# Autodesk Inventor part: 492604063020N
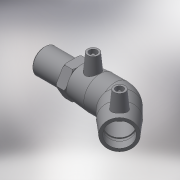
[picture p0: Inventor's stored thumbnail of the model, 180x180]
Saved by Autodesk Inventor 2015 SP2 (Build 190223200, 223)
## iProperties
Created: 2017-06
Part Number: 492604063020N
Material: Generic
Description: PLASSON 45° ELBOW TRANSITION MALE 63 x 2"
Document SubType Name: Modeling
Designer: KIM
Mass: 541.939 g
Surface Area: 967.29 cm^2
Volume: 541.939 cm^3
Density: 1 g/cm^3
Appearance: Default
Author: KIM
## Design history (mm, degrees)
derived "492604.ipt"
feature "Solid1::492604.ipt"
tag "TaggingFeature1"
body "Solid1"
other parameters: "d2" = 82, "d4" = 36.75, "d5" = 73.8, "d8" = 168 deg, "d10" = 23.2, "d11" = 7.73333, "d29" = 57, "d30" = 15, "d31" = 51.45, "d34" = 5 deg, "d41" = 4, "d42" = 14, "d43" = 0, "d49" = 63, "d50" = 40.95, "d51" = 23.2, "d52" = 59.74, "d54" = 135 deg, "d86" = 36.9, "d87" = 135 deg, "d88" = 147, "d90" = 58, "d91" = 0, "d92" = 58, "d93" = 0, "d101" = 3, "d102" = 0, "d107" = 0.1, "d108" = 47, "d109" = 59.614, "d110" = 68, "d111" = 17, "d112" = 82, "d113" = 41.7298, "d114" = 61.2, "d116" = 2.46, "d122" = 0, "d123" = 2.9807, "d_" = 63, "L_" = 215, "L_1" = 58, "D_" = 47, "A_" = 57, "d_2" = 12, "L_2" = 68, "R_" = 59.614, "D_1" = 82
